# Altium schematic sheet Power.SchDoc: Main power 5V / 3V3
size A4; Date: Not used; ApprovedBy: Not used; CheckedBy: Not used; Author: Not used; CompanyName: STMicroelectronics; DrawnBy: Not used; Engineer: Not used; Organization: Not used; Address1: Not used; Address2: Not used; Address3: Not used; Address4: Not used; DocumentNumber: 6; Revision: Not used; SheetNumber: 6; SheetTotal: 8
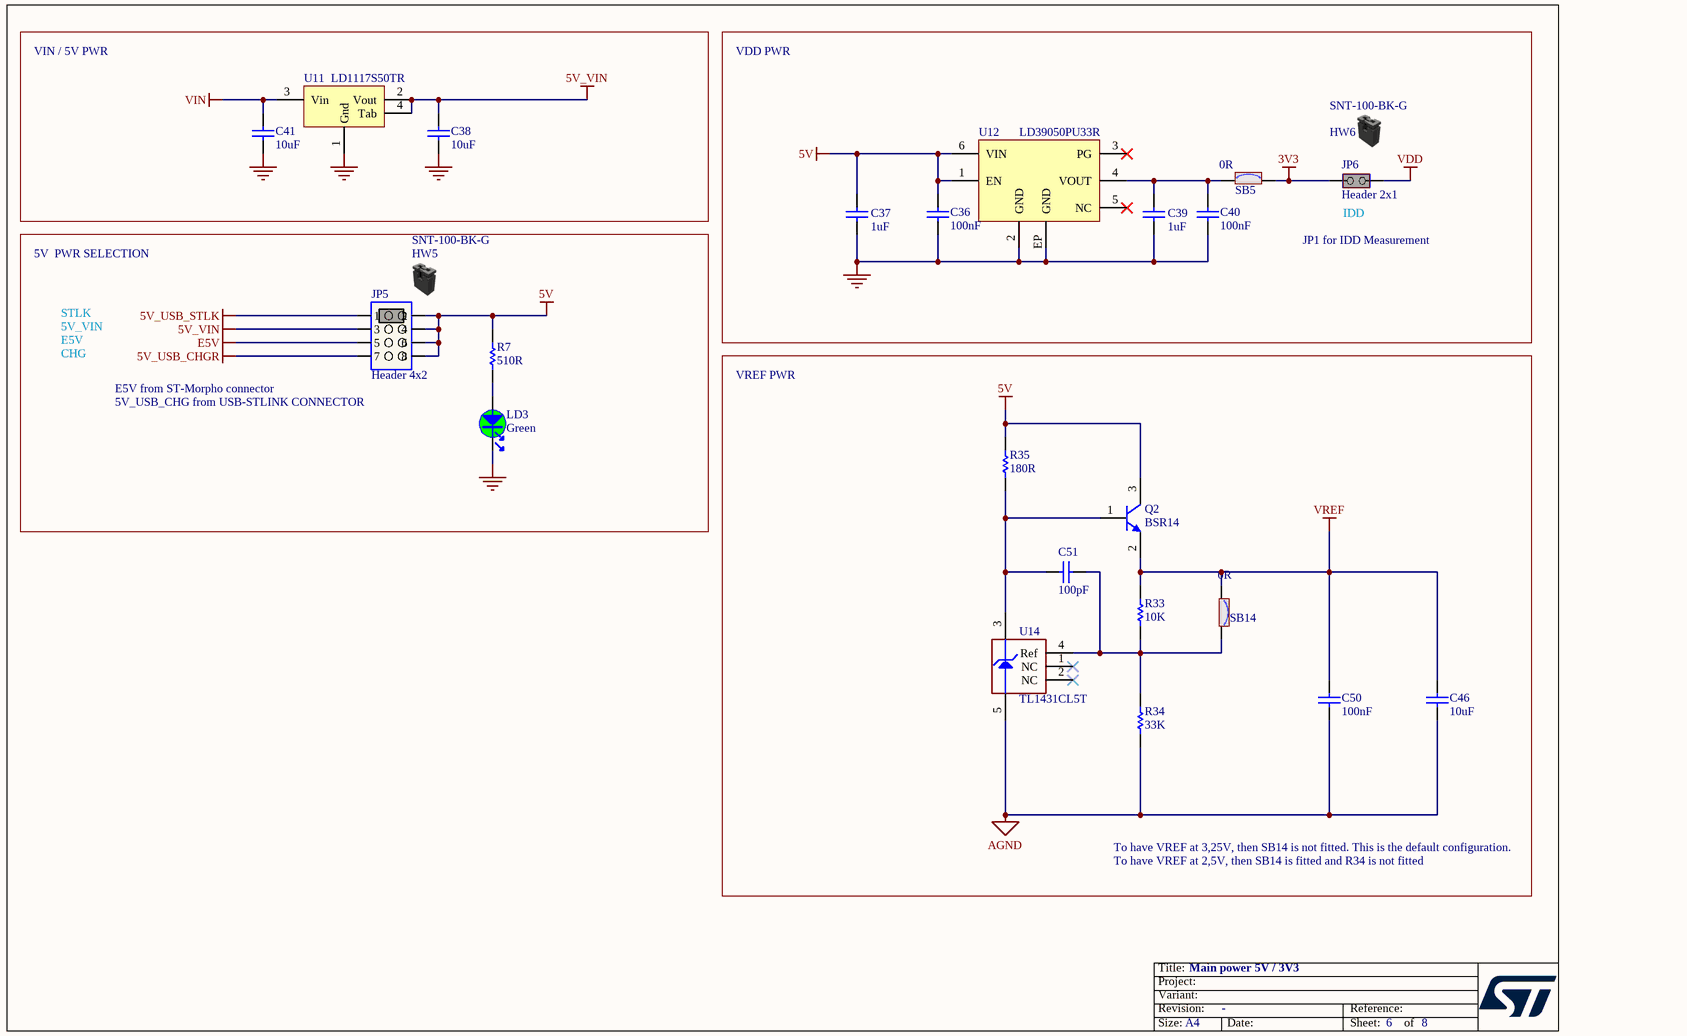
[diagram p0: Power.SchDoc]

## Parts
C36  value 100nF  [C0402]  (hidden comment: Capacitor)
C37  value 1uF  [C0603]
C38  value 10uF  [C0805]
C39  value 1uF  [C0603]
C40  value 100nF  [C0402]  (hidden comment: Capacitor)
C41  value 10uF  [C0805]
C46  value 10uF  [C0603]
C50  value 100nF  [C0603]
C51  value 100pF  [C0603]
HW5  value SNT-100-BK-G  (mechanical)
HW6  value SNT-100-BK-G  (mechanical)
JP5  value Header 4x2  [CON_SAMTEC_TSW-104-07-X-D]
JP6  value Header 2x1  [CON_SAMTEC_TSW-102-07-G-S]  (hidden comment: Shunt Fitted)
LD3  value Green  [LED_0603_GREEN]  (hidden comment: LED_green)
Q2  value BSR14  [NPN_SOT23]
R7  value 510R  [R0603]
R33  value 10K  [R0603]
R34  value 33K  [R0603]
R35  value 180R  [R0603]
SB5  value 0R  [SOLDER-BRIDGE_R0603-0R]
SB14  value 0R  [SOLDER-BRIDGE_R0603-0R]
U11  value LD1117S50TR  [REG_SOT223-TAB]
U12  value LD39050PU33R  [ICC_DFN6-EPAD_3X3_P095]
U14  value TL1431CL5T  [ICC_SOT23-5L_H1P45]

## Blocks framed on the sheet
VIN / 5V PWR: C38 C41 U11
VREF PWR: C46 C50 C51 Q2 R33-R35 SB14 U14

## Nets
3V3: JP6.1(COMMON) SB5.2
5V: C36.2 C37.2 JP5.2 JP5.4 JP5.6 JP5.8 Q2.3(C) R7.2 R35.2 U12.1(EN) U12.6(VIN)
5V_USB_CHGR: JP5.7
5V_USB_STLK: JP5.1
5V_VIN: C38.2 JP5.3 U11.2(Vout) U11.4(Tab)
AGND: C46.1 C50.1 R34.1 U14.5(Anode)
E5V: JP5.5
GND: C36.1 C37.1 C38.1 C39.1 C40.1 C41.1 LD3.2 U11.1(Gnd) U12.2(GND) U12.EP(GND)
VDD: JP6.2(NO)
VIN: C41.2 U11.3(Vin)
VREF: C46.2 C50.2 Q2.2(E) R33.2 SB14.1
NetC39_2: C39.2 C40.2 SB5.1 U12.4(VOUT)
NetC51_1: C51.1 Q2.1(B) R35.1 U14.3(Cathode)
NetC51_2: C51.2 R33.1 R34.2 SB14.2 U14.4(Ref)
NetLD3_1: LD3.1 R7.1

Not connected (* = marked no-connect by the designer): U12 3(PG)* 5(NC)*; U14 1(NC)* 2(NC)*

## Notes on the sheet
- VDD PWR
- JP1 for IDD Measurement
- (near JP6) IDD
- 5V  PWR SELECTION
- STLK
- E5V
- 5V_VIN
- CHG
- E5V from ST-Morpho connector
- 5V_USB_CHG from USB-STLINK CONNECTOR
- To have VREF at 3,25V, then SB14 is not fitted. This is the default configuration.
- To have VREF at 2,5V, then SB14 is fitted and R34 is not fitted

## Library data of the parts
C36 C40 = MCD-00006: Capacitor, MLCC, 100nF, 16V, X7R, +/-10%, 0402, T=0.5mm; Manufacturer_Part_Number: CC0402KRX7R7BB104; Manufacturer: YAGEO; Part_Preference: Recommended; Partial_Alternate_Internal_Part_Number: MCD-03299; Order_Code_RS: 9402047; Component_Country_Of_Origin: China; ShowFields: YES; ID: 2474
C37 C39 = MCD-00010: Capacitor, MLCC, 1uF, 16V, X5R, 10%, 0603, T=0,8mm; Manufacturer_Part_Number: CC0603KRX5R7BB105; Manufacturer: YAGEO; Part_Preference: Recommended; Provided_By: Subcon; Initial_Board_Reference: MB1274; Component_Country_Of_Origin: China; ID: 2470; Order_Code_RS: 2370680; ShowFields: YES
C38 C41 = MCD-00014: Capacitor, MLCC, 10uF, 25V, X5R, 10%, 0805, T=0,85mm; Manufacturer_Part_Number: CC0805KRX5R8BB106; Manufacturer: YAGEO; Full_Alternate_Internal_Part_Number: MCD-02385; Part_Preference: Recommended; Partial_Alternate_Internal_Part_Number: MCD-03053; ECCN_US: EAR99; ECCN_EU: NEC; Provided_By: SUBCO; Component_Country_Of_Origin: China; ID: 2468; ShowFields: YES
C46 = MCD-01124: Capacitor, MLCC, 10uF, 10V, X5R, 10%, 0603, T=0.8mm; Manufacturer_Part_Number: GRM188R61A106KAAL; Manufacturer: MURATA; Part_Preference: Recommended; Partial_Alternate_Internal_Part_Number: MCD-03152; ECCN_US: EAR99; ECCN_EU: NEC; Provided_By: SUBCO; Component_Country_Of_Origin: Japan°°; ID: 3372; Order_Code_RS: 170-6258; ShowFields: YES
C50 = MCD-00211: Capacitor, MLCC, 100nF, 16V, X7R, 10%, 0603, T=0,8mm; Manufacturer_Part_Number: CC0603KRX7R7BB104; Manufacturer: YAGEO; Part_Preference: Recommended; Partial_Alternate_Internal_Part_Number: MCD-01099; ECCN_US: EAR99; ECCN_EU: NEC; Provided_By: SUBCO; Component_Country_Of_Origin: China; ID: 2659; Order_Code_RS: 669-8763; ShowFields: YES
C51 = MCD-01101: Capacitor,100pF,50V,X7R,10%,0603; Manufacturer_Part_Number: 06035C101JAT4A; Manufacturer: KYOCERA AVX; Part_Preference: Recommended; ECCN_US: EAR99; ECCN_EU: NEC; Provided_By: SUBCO; Component_Country_Of_Origin: China; ID: 3399; ShowFields: YES
HW5 HW6 = MCD-00043: SHUNT 2.54mm BLACK; Manufacturer: SAMTEC; Part_Type: Misc; Manufacturer_HQ_COO: Unknown; Part_Preference: Recommended; Partial_Alternate_Internal_Part_Number: MCD-01849, MCD-01864, MCD-02388, MCD-03991, MCD-04284, MCD-04580; Provided_By: Subcon; Initial_Board_Reference: MB1274; Alternate_EMS: A; Component_Country_Of_Origin: China, Costa Rica, Malaysia, USA, Vietnam; ID: 2551; Order_Code_RS: 158-7784; ShowFields: YES
JP5 = MCD-00686: Header, 4x2, 2,54mm, VR, TH, Height 5.84mm/2.54mm - Shunt Fitted 1-2; Part_Type: Connector; Manufacturer_Part_Number: TSW-104-07-G-D; Manufacturer: SAMTEC; Part_Preference: Recommended; Partial_Alternate_Internal_Part_Number: MCD-01661, MCD-03721, MCD-03993; Provided_By: SUBCO; Component_Country_Of_Origin: China, Costa Rica, Malaysia, USA, Vietnam; ID: 3062; Order_Code_RS: 161-2260; ShowFields: YES
JP6 = MCD-00683: Header, 2x1, 2,54mm, VR, TH, Height 5.84mm/2.54mm - Shunt Fitted by default; Part_Type: Connector; Manufacturer_Part_Number: TSW-102-07-G-S; Manufacturer: SAMTEC; Part_Preference: Recommended; Partial_Alternate_Internal_Part_Number: MCD-02389, MCD-02957, MCD-03720, MCD-03979, MCD-04463; Provided_By: Subcon; Initial_Board_Reference: MB1331; Component_Country_Of_Origin: China, Costa Rica, Malaysia, USA, Vietnam; ID: 3057; Order_Code_RS: 155-5312; ShowFields: YES
LD3 = MCD-02900: LED, Green, 2V, 20mA, 0603; Part_Type: Display; Part_Preference: Recommended; Manufacturer: EVERLIGHT; Manufacturer_Part_Number: 19-213SYGC/S530-E2/5T; Full_Alternate_Internal_Part_Number: MCD-00320; Partial_Alternate_Internal_Part_Number: MCD-00050; ShowFields: YES; ID: 5016; Component_Country_Of_Origin: China
Q2 = MCD-00073: NPN Bipolar Transistor; Manufacturer: ON SEMICONDUCTOR; Alternate_Manufacturer_Part_Number: MMBT2222LT1G / MMBT2222ALT1G / MMBT2222ALT3G; Part_Preference: Recommended; Partial_Alternate_Internal_Part_Number: MCD-01737, MCD-03305, MCD-02988; ECCN_US: EAR99; ECCN_EU: NEC; Provided_By: SUBCO; Component_Country_Of_Origin: Unknown; ID: 2519; ShowFields: YES
R7 = MCD-00225: Resistor,510R,0603,1%,1/10W; Manufacturer_Part_Number: RC0603FR-07510RL; Manufacturer: YAGEO; Part_Preference: Recommended; ECCN_US: EAR99; ECCN_EU: NEC; Provided_By: SUBCO; Component_Country_Of_Origin: China; ID: 2644; ShowFields: YES
R33 = MCD-01215: resistor, 10K, 0603, 0.5%, 1/10W; Manufacturer_Part_Number: RC0603DR-0710KL; Manufacturer: YAGEO; Part_Preference: Recommended; ECCN_US: EAR99; ECCN_EU: NEC; Provided_By: SUBCO; Component_Country_Of_Origin: China; ID: 3280; ShowFields: YES
R34 = MCD-01209: Resistor,33K,0603,0.5%,1/10W; Manufacturer_Part_Number: RC0603DR-0733KL; Manufacturer: YAGEO; Part_Preference: Recommended; ECCN_US: EAR99; ECCN_EU: NEC; Provided_By: SUBCO; Component_Country_Of_Origin: China; ID: 3286; ShowFields: YES
R35 = MCD-00342: Resistor,180R,0603,1%,1/10W; Manufacturer_Part_Number: RC0603FR-07180RL; Manufacturer: YAGEO; Part_Preference: Recommended; ECCN_US: EAR99; ECCN_EU: NEC; Provided_By: SUBCO; Component_Country_Of_Origin: China; ID: 2936; ShowFields: YES
SB5 SB14 = MCD-00071: Solder Bridge ON; Part_Type: Resistor; Manufacturer_Part_Number: RC0603JR-070RL; Manufacturer: YAGEO; Manufacturer_HQ_COO: Unknown; Part_Preference: Recommended; Provided_By: SUBCO; Component_Country_Of_Origin: China; ID: 2521; Order_Code_RS: 199-5647; ShowFields: YES
U11 = MCD-00088: IC REG LDO 5V 0.8A SOT223; Manufacturer: STMICROELECTRONICS; BMS_Part_Number: 9176133; Manufacturer_HQ_COO: EU; Part_Preference: Recommended; ECCN_US: EAR99; ECCN_EU: NEC; Provided_By: SUBCO with ST control; Component_Country_Of_Origin: China; ID: 2503; Order_Code_RS: 165-7748; ShowFields: YES
U12 = MCD-00215: Low quiescent current and low noise voltage regulators; Manufacturer: STMICROELECTRONICS; Part_Type: IC; BMS_Part_Number: 9176126; Part_Preference: Recommended; ECCN_US: EAR99; ECCN_EU: NEC; Provided_By: SUBCO with ST control; Component_Country_Of_Origin: Malaysia; ID: 2654; Order_Code_RS: 196-1948; ShowFields: YES
U14 = MCD-01802: Programmable voltage reference with 0.4% voltage precision; Part_Type: IC; Manufacturer: STMICROELECTRONICS; BMS_Part_Number: 9176334; Manufacturer_HQ_COO: EU; Part_Preference: Recommended; ECCN_US: EAR99; ECCN_EU: NEC; Provided_By: SUBCO with ST control; Component_Country_Of_Origin: Malaysia; ID: 3902; ShowFields: YES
